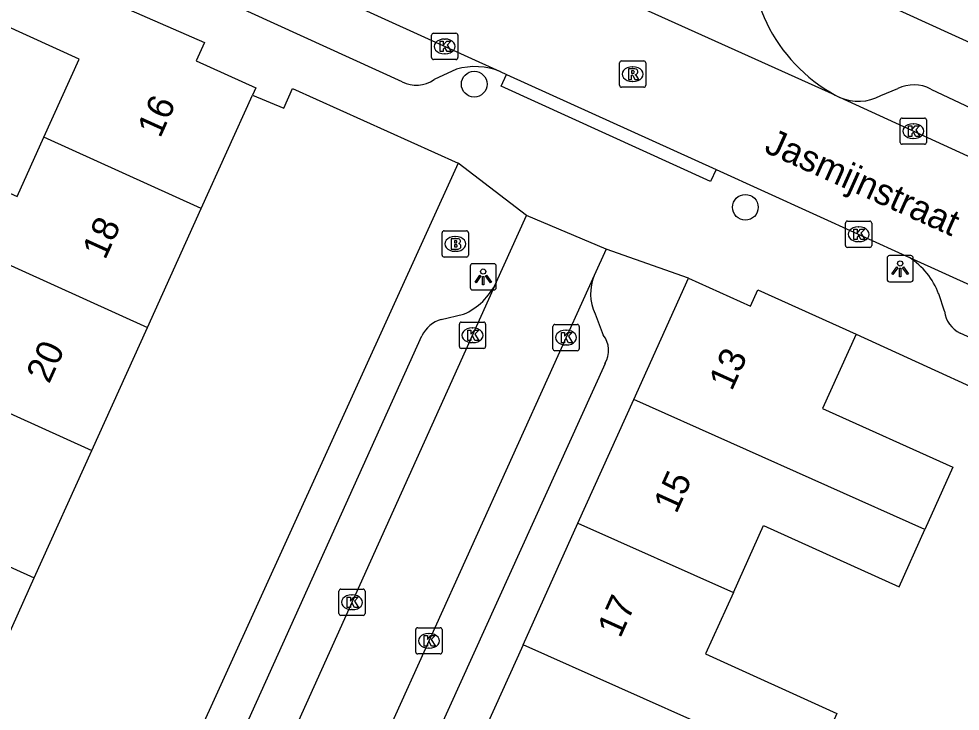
# Model space of a CAD drawing. Extents: x 161845 to 162341, y 381620 to 382158.
# Drawn here: x 162073.02 to 162108.87, y 381765.94 to 381792.29 of the extents above; entities that cross this region are included whole.
import ezdxf

# ---------------------------------------------------------------- set-up
doc = ezdxf.new("R2010")
doc.units = 0
for name, color, linetype in [('IMGEO_Boom', 7, 'Continuous'), ('IMGEO_Brandkraan', 7, 'Continuous'), ('IMGEO_Kolk', 7, 'Continuous'), ('IMGEO_Lichtpunt', 7, 'Continuous'), ('IMGEO_Muur', 7, 'Continuous'), ('IMGEO_Openbare_ruimte_label', 7, 'Continuous'), ('IMGEO_Pand', 7, 'Continuous'), ('IMGEO_Pand_nummerreeks', 7, 'Continuous'), ('IMGEO_Rijbaan_lokaal_open', 7, 'Continuous'), ('IMGEO_Rioolput', 7, 'Continuous'), ('IMGEO_Voetpad_open', 7, 'Continuous')]:
    doc.layers.add(name, color=color, linetype=linetype)

msp = doc.modelspace()

# ---------------------------------------------------------------- linework, layer by layer
at = {"layer": 'IMGEO_Boom'}
for centre in [(162090.359, 381789.808), (162100.687, 381785.121)]:
    msp.add_circle(centre, 0.489, dxfattribs=at)
at = {"layer": 'IMGEO_Brandkraan'}
for p, q in [((162089.138, 381783.301), (162089.138, 381784.153)), ((162089.213, 381784.227), (162090.065, 381784.227)), ((162089.626, 381784.007), (162089.651, 381784.007)), ((162090.139, 381784.153), (162090.139, 381783.301)), ((162089.649, 381783.447), (162089.624, 381783.447)), ((162090.065, 381783.227), (162089.213, 381783.227))]:
    msp.add_line(p, q, dxfattribs=at)
for points in [[(162089.138, 381783.301), (162089.138, 381784.153)], [(162089.213, 381784.227), (162090.065, 381784.227)], [(162090.139, 381784.153), (162090.139, 381783.301)], [(162089.486, 381783.927), (162089.486, 381783.527), (162089.699, 381783.527)], [(162089.717, 381783.927), (162089.486, 381783.927)], [(162089.665, 381783.846), (162089.611, 381783.846), (162089.611, 381783.77)], [(162089.611, 381783.77), (162089.664, 381783.77)], [(162089.673, 381783.694), (162089.611, 381783.694), (162089.611, 381783.613)], [(162089.611, 381783.613), (162089.673, 381783.613)], [(162090.065, 381783.227), (162089.213, 381783.227)]]:
    msp.add_lwpolyline(points, dxfattribs=at)
for centre, radius, start, end in [((162089.215, 381784.151), 0.0765, 91.552, 178.448), ((162089.215, 381784.151), 0.0765, 91.552, 178.448), ((162090.063, 381784.151), 0.0765, 1.552, 88.448), ((162090.063, 381784.151), 0.0765, 1.552, 88.448), ((162089.666, 381783.808), 0.0379, 267.8285, 90.9355), ((162089.674, 381783.653), 0.0404, 269.8759, 90.5077), ((162089.721, 381783.782), 0.145, 59.4692, 91.5367), ((162089.746, 381783.829), 0.0922, 285.5137, 58.1501), ((162089.751, 381783.637), 0.105, 301.3115, 78.989), ((162089.215, 381783.303), 0.0765, 181.552, 268.448), ((162089.215, 381783.303), 0.0765, 181.552, 268.448), ((162089.705, 381783.778), 0.251, 268.6676, 293.5347), ((162090.063, 381783.303), 0.0765, 271.552, 358.448), ((162090.063, 381783.303), 0.0765, 271.552, 358.448)]:
    msp.add_arc(centre, radius, start, end, dxfattribs=at)
for centre, major_axis, ratio, start_param, end_param in [((162089.625, 381783.727), (-0.387, 0.002), 0.722429, 4.712389, 7.853982), ((162089.65, 381783.727), (-0.39, 0.002), 0.717154, 1.570796, 4.712389)]:
    msp.add_ellipse(centre, major_axis=major_axis, ratio=ratio, start_param=start_param, end_param=end_param, dxfattribs=at)
at = {"layer": 'IMGEO_Kolk'}
for p, q in [((162088.737, 381790.82), (162088.737, 381791.672)), ((162088.812, 381791.746), (162089.664, 381791.746)), ((162089.225, 381791.526), (162089.25, 381791.526)), ((162089.738, 381791.672), (162089.738, 381790.82)), ((162089.248, 381790.966), (162089.223, 381790.966)), ((162089.664, 381790.746), (162088.812, 381790.746)), ((162106.584, 381787.594), (162106.584, 381788.446)), ((162106.659, 381788.52), (162107.511, 381788.52)), ((162107.072, 381788.3), (162107.097, 381788.3)), ((162107.585, 381788.446), (162107.585, 381787.594)), ((162107.095, 381787.74), (162107.07, 381787.74)), ((162107.511, 381787.52), (162106.659, 381787.52)), ((162104.497, 381783.668), (162104.497, 381784.52)), ((162104.572, 381784.594), (162105.424, 381784.594)), ((162104.985, 381784.374), (162105.01, 381784.374)), ((162105.498, 381784.52), (162105.498, 381783.668)), ((162105.424, 381783.594), (162104.572, 381783.594)), ((162105.008, 381783.814), (162104.983, 381783.814)), ((162089.868, 381780.75), (162090.72, 381780.75)), ((162089.793, 381779.824), (162089.793, 381780.676)), ((162090.281, 381780.53), (162090.306, 381780.53)), ((162090.794, 381780.676), (162090.794, 381779.824)), ((162093.357, 381779.736), (162093.357, 381780.588)), ((162093.432, 381780.662), (162094.284, 381780.662)), ((162093.845, 381780.442), (162093.87, 381780.442)), ((162094.358, 381780.588), (162094.358, 381779.736)), ((162090.72, 381779.75), (162089.868, 381779.75)), ((162090.304, 381779.97), (162090.279, 381779.97)), ((162094.284, 381779.662), (162093.432, 381779.662)), ((162093.868, 381779.882), (162093.843, 381779.882)), ((162085.204, 381769.662), (162085.204, 381770.514)), ((162085.279, 381770.588), (162086.131, 381770.588)), ((162085.692, 381770.368), (162085.717, 381770.368)), ((162086.205, 381770.514), (162086.205, 381769.662)), ((162085.715, 381769.808), (162085.69, 381769.808)), ((162086.131, 381769.588), (162085.279, 381769.588)), ((162088.134, 381768.195), (162088.134, 381769.047)), ((162088.209, 381769.121), (162089.061, 381769.121)), ((162088.622, 381768.901), (162088.647, 381768.901)), ((162089.135, 381769.047), (162089.135, 381768.195)), ((162088.645, 381768.341), (162088.62, 381768.341)), ((162089.061, 381768.121), (162088.209, 381768.121))]:
    msp.add_line(p, q, dxfattribs=at)
for points in [[(162088.737, 381790.82), (162088.737, 381791.672)], [(162088.812, 381791.746), (162089.664, 381791.746)], [(162089.738, 381791.672), (162089.738, 381790.82)], [(162089.058, 381791.446), (162089.181, 381791.446), (162089.181, 381791.295), (162089.311, 381791.446), (162089.475, 381791.446), (162089.329, 381791.295), (162089.482, 381791.046), (162089.33, 381791.046), (162089.245, 381791.21), (162089.181, 381791.143), (162089.181, 381791.046), (162089.058, 381791.046), (162089.058, 381791.446)], [(162089.664, 381790.746), (162088.812, 381790.746)], [(162106.584, 381787.594), (162106.584, 381788.446)], [(162106.659, 381788.52), (162107.511, 381788.52)], [(162107.585, 381788.446), (162107.585, 381787.594)], [(162106.905, 381788.22), (162107.028, 381788.22), (162107.028, 381788.069), (162107.158, 381788.22), (162107.322, 381788.22), (162107.176, 381788.069), (162107.329, 381787.82), (162107.177, 381787.82), (162107.092, 381787.984), (162107.028, 381787.917), (162107.028, 381787.82), (162106.905, 381787.82), (162106.905, 381788.22)], [(162107.511, 381787.52), (162106.659, 381787.52)], [(162104.497, 381783.668), (162104.497, 381784.52)], [(162104.572, 381784.594), (162105.424, 381784.594)], [(162105.498, 381784.52), (162105.498, 381783.668)], [(162104.818, 381784.294), (162104.941, 381784.294), (162104.941, 381784.143), (162105.071, 381784.294), (162105.235, 381784.294), (162105.089, 381784.143), (162105.242, 381783.894), (162105.09, 381783.894), (162105.005, 381784.058), (162104.941, 381783.991), (162104.941, 381783.894), (162104.818, 381783.894), (162104.818, 381784.294)], [(162105.424, 381783.594), (162104.572, 381783.594)], [(162089.868, 381780.75), (162090.72, 381780.75)], [(162089.793, 381779.824), (162089.793, 381780.676)], [(162090.114, 381780.45), (162090.237, 381780.45), (162090.237, 381780.299), (162090.367, 381780.45), (162090.531, 381780.45), (162090.385, 381780.299), (162090.538, 381780.05), (162090.386, 381780.05), (162090.301, 381780.214), (162090.237, 381780.147), (162090.237, 381780.05), (162090.114, 381780.05), (162090.114, 381780.45)], [(162090.794, 381780.676), (162090.794, 381779.824)], [(162093.357, 381779.736), (162093.357, 381780.588)], [(162093.432, 381780.662), (162094.284, 381780.662)], [(162094.358, 381780.588), (162094.358, 381779.736)], [(162093.678, 381780.362), (162093.801, 381780.362), (162093.801, 381780.211), (162093.931, 381780.362), (162094.095, 381780.362), (162093.949, 381780.211), (162094.102, 381779.962), (162093.95, 381779.962), (162093.865, 381780.126), (162093.801, 381780.059), (162093.801, 381779.962), (162093.678, 381779.962), (162093.678, 381780.362)], [(162090.72, 381779.75), (162089.868, 381779.75)], [(162094.284, 381779.662), (162093.432, 381779.662)], [(162085.204, 381769.662), (162085.204, 381770.514)], [(162085.279, 381770.588), (162086.131, 381770.588)], [(162086.205, 381770.514), (162086.205, 381769.662)], [(162085.525, 381770.288), (162085.648, 381770.288), (162085.648, 381770.137), (162085.778, 381770.288), (162085.942, 381770.288), (162085.796, 381770.137), (162085.949, 381769.888), (162085.797, 381769.888), (162085.712, 381770.052), (162085.648, 381769.985), (162085.648, 381769.888), (162085.525, 381769.888), (162085.525, 381770.288)], [(162086.131, 381769.588), (162085.279, 381769.588)], [(162088.134, 381768.195), (162088.134, 381769.047)], [(162088.209, 381769.121), (162089.061, 381769.121)], [(162089.135, 381769.047), (162089.135, 381768.195)], [(162088.455, 381768.821), (162088.578, 381768.821), (162088.578, 381768.67), (162088.708, 381768.821), (162088.872, 381768.821), (162088.726, 381768.67), (162088.879, 381768.421), (162088.727, 381768.421), (162088.642, 381768.585), (162088.578, 381768.518), (162088.578, 381768.421), (162088.455, 381768.421), (162088.455, 381768.821)], [(162089.061, 381768.121), (162088.209, 381768.121)]]:
    msp.add_lwpolyline(points, dxfattribs=at)
for centre, start, end in [((162088.814, 381791.67), 91.552, 178.448), ((162088.814, 381791.67), 91.552, 178.448), ((162089.662, 381791.67), 1.552, 88.448), ((162089.662, 381791.67), 1.552, 88.448), ((162088.814, 381790.822), 181.552, 268.448), ((162088.814, 381790.822), 181.552, 268.448), ((162089.662, 381790.822), 271.552, 358.448), ((162089.662, 381790.822), 271.552, 358.448), ((162106.661, 381788.444), 91.552, 178.448), ((162106.661, 381788.444), 91.552, 178.448), ((162107.509, 381788.444), 1.552, 88.448), ((162107.509, 381788.444), 1.552, 88.448), ((162106.661, 381787.596), 181.552, 268.448), ((162106.661, 381787.596), 181.552, 268.448), ((162107.509, 381787.596), 271.552, 358.448), ((162107.509, 381787.596), 271.552, 358.448), ((162104.574, 381784.518), 91.552, 178.448), ((162104.574, 381784.518), 91.552, 178.448), ((162105.422, 381784.518), 1.552, 88.448), ((162105.422, 381784.518), 1.552, 88.448), ((162104.574, 381783.67), 181.552, 268.448), ((162104.574, 381783.67), 181.552, 268.448), ((162105.422, 381783.67), 271.552, 358.448), ((162105.422, 381783.67), 271.552, 358.448), ((162089.87, 381780.674), 91.552, 178.448), ((162089.87, 381780.674), 91.552, 178.448), ((162090.718, 381780.674), 1.552, 88.448), ((162090.718, 381780.674), 1.552, 88.448), ((162093.434, 381780.586), 91.552, 178.448), ((162093.434, 381780.586), 91.552, 178.448), ((162094.282, 381780.586), 1.552, 88.448), ((162094.282, 381780.586), 1.552, 88.448), ((162089.87, 381779.826), 181.552, 268.448), ((162089.87, 381779.826), 181.552, 268.448), ((162090.718, 381779.826), 271.552, 358.448), ((162090.718, 381779.826), 271.552, 358.448), ((162093.434, 381779.738), 181.552, 268.448), ((162093.434, 381779.738), 181.552, 268.448), ((162094.282, 381779.738), 271.552, 358.448), ((162094.282, 381779.738), 271.552, 358.448), ((162085.281, 381770.512), 91.552, 178.448), ((162085.281, 381770.512), 91.552, 178.448), ((162086.129, 381770.512), 1.552, 88.448), ((162086.129, 381770.512), 1.552, 88.448), ((162085.281, 381769.664), 181.552, 268.448), ((162085.281, 381769.664), 181.552, 268.448), ((162086.129, 381769.664), 271.552, 358.448), ((162086.129, 381769.664), 271.552, 358.448), ((162088.211, 381769.045), 91.552, 178.448), ((162088.211, 381769.045), 91.552, 178.448), ((162089.059, 381769.045), 1.552, 88.448), ((162089.059, 381769.045), 1.552, 88.448), ((162088.211, 381768.197), 181.552, 268.448), ((162088.211, 381768.197), 181.552, 268.448), ((162089.059, 381768.197), 271.552, 358.448), ((162089.059, 381768.197), 271.552, 358.448)]:
    msp.add_arc(centre, 0.0765, start, end, dxfattribs=at)
for centre, major_axis, ratio, start_param, end_param in [((162089.224, 381791.246), (-0.387, 0.002), 0.722429, 4.712389, 7.853982), ((162089.249, 381791.246), (-0.39, 0.002), 0.717154, 1.570796, 4.712389), ((162107.071, 381788.02), (-0.387, 0.002), 0.722429, 4.712389, 7.853982), ((162107.096, 381788.02), (-0.39, 0.002), 0.717154, 1.570796, 4.712389), ((162104.984, 381784.094), (-0.387, 0.002), 0.722429, 4.712389, 7.853982), ((162105.009, 381784.094), (-0.39, 0.002), 0.717154, 1.570796, 4.712389), ((162090.28, 381780.25), (-0.387, 0.002), 0.722429, 4.712389, 7.853982), ((162090.305, 381780.25), (-0.39, 0.002), 0.717154, 1.570796, 4.712389), ((162093.844, 381780.162), (-0.387, 0.002), 0.722429, 4.712389, 7.853982), ((162093.869, 381780.162), (-0.39, 0.002), 0.717154, 1.570796, 4.712389), ((162085.691, 381770.088), (-0.387, 0.002), 0.722429, 4.712389, 7.853982), ((162085.716, 381770.088), (-0.39, 0.002), 0.717154, 1.570796, 4.712389), ((162088.621, 381768.621), (-0.387, 0.002), 0.722429, 4.712389, 7.853982), ((162088.646, 381768.621), (-0.39, 0.002), 0.717154, 1.570796, 4.712389)]:
    msp.add_ellipse(centre, major_axis=major_axis, ratio=ratio, start_param=start_param, end_param=end_param, dxfattribs=at)
at = {"layer": 'IMGEO_Lichtpunt'}
for p, q in [((162106.986, 381783.282), (162106.178, 381783.282)), ((162106.986, 381783.282), (162106.178, 381783.282)), ((162090.205, 381782.877), (162090.205, 381782.07)), ((162090.205, 381782.877), (162090.205, 381782.07)), ((162091.107, 381782.972), (162090.299, 381782.972)), ((162091.107, 381782.972), (162090.299, 381782.972)), ((162091.201, 381782.07), (162091.201, 381782.877)), ((162091.201, 381782.07), (162091.201, 381782.877)), ((162106.084, 381783.187), (162106.084, 381782.38)), ((162106.084, 381783.187), (162106.084, 381782.38)), ((162107.08, 381782.38), (162107.08, 381783.187)), ((162107.08, 381782.38), (162107.08, 381783.187)), ((162106.178, 381782.286), (162106.986, 381782.286)), ((162106.178, 381782.286), (162106.986, 381782.286)), ((162090.299, 381781.976), (162091.107, 381781.976)), ((162090.299, 381781.976), (162091.107, 381781.976))]:
    msp.add_line(p, q, dxfattribs=at)
for points in [[(162090.579, 381782.541), (162090.618, 381782.513), (162090.43, 381782.251), (162090.392, 381782.278), (162090.579, 381782.541)], [(162090.791, 381782.513), (162090.829, 381782.54), (162091.016, 381782.278), (162090.977, 381782.25), (162090.791, 381782.513)], [(162106.458, 381782.851), (162106.497, 381782.823), (162106.309, 381782.561), (162106.271, 381782.588), (162106.458, 381782.851)], [(162106.56, 381782.803), (162106.607, 381782.803), (162106.607, 381782.481), (162106.56, 381782.481), (162106.56, 381782.803)], [(162106.67, 381782.823), (162106.708, 381782.85), (162106.895, 381782.588), (162106.856, 381782.56), (162106.67, 381782.823)], [(162090.681, 381782.493), (162090.728, 381782.493), (162090.728, 381782.171), (162090.681, 381782.171), (162090.681, 381782.493)]]:
    msp.add_lwpolyline(points, dxfattribs=at)
for centre in [(162106.583, 381782.985), (162090.704, 381782.675)]:
    msp.add_circle(centre, 0.0994, dxfattribs=at)
for centre, start, end in [((162106.178, 381783.187), 90, 180), ((162106.178, 381783.187), 90, 180), ((162106.986, 381783.187), 0, 90), ((162106.986, 381783.187), 0, 90), ((162090.299, 381782.877), 90, 180), ((162090.299, 381782.877), 90, 180), ((162091.107, 381782.877), 0, 90), ((162091.107, 381782.877), 0, 90), ((162106.178, 381782.38), 180, 270), ((162106.178, 381782.38), 180, 270), ((162106.986, 381782.38), 270, 0), ((162106.986, 381782.38), 270, 360), ((162090.299, 381782.07), 180, 270), ((162090.299, 381782.07), 180, 270), ((162091.107, 381782.07), 270, 0), ((162091.107, 381782.07), 270, 360)]:
    msp.add_arc(centre, 0.0946, start, end, dxfattribs=at)
at = {"layer": 'IMGEO_Muur'}
msp.add_lwpolyline([(162104.902, 381780.293), (162119.551, 381773.591)], dxfattribs=at)
at = {"layer": 'IMGEO_Pand'}
for points in [[(162073.969, 381787.795), (162075.316, 381790.766), (162070.431, 381792.976), (162071.424, 381795.171)], [(162071.424, 381795.171), (162080.088, 381791.39), (162079.775, 381790.698), (162082.043, 381789.672), (162081.916, 381789.39)], [(162109.58, 381791.299), (162109.557, 381791.247), (162105.823, 381792.94), (162106.121, 381793.596), (162103.999, 381794.559)], [(162079.965, 381785.079), (162081.916, 381789.39)], [(162066.965, 381785.512), (162067.993, 381787.785), (162072.946, 381785.539), (162073.969, 381787.795)], [(162079.965, 381785.079), (162073.969, 381787.795)], [(162066.965, 381785.512), (162077.918, 381780.552)], [(162077.918, 381780.552), (162079.965, 381785.079)], [(162096.439, 381777.811), (162098.526, 381782.429)], [(162098.526, 381782.429), (162100.887, 381781.363), (162101.163, 381781.976), (162104.902, 381780.293)], [(162075.797, 381775.863), (162077.918, 381780.552)], [(162104.902, 381780.293), (162103.63, 381777.467), (162108.591, 381775.234), (162107.525, 381772.865)], [(162069.789, 381778.584), (162075.797, 381775.863)], [(162094.311, 381773.1), (162096.439, 381777.811)], [(162107.525, 381772.865), (162096.439, 381777.811)], [(162062.654, 381775.972), (162073.603, 381771.013)], [(162073.603, 381771.013), (162075.797, 381775.863)], [(162092.219, 381768.471), (162094.311, 381773.1)], [(162094.311, 381773.1), (162100.229, 381770.46)], [(162100.229, 381770.46), (162101.379, 381773.006), (162106.539, 381770.675), (162107.525, 381772.865)], [(162071.478, 381766.316), (162073.603, 381771.013)], [(162100.229, 381770.46), (162099.172, 381768.121), (162104.172, 381765.858), (162103.149, 381763.595)], [(162092.219, 381768.471), (162090.043, 381763.653)], [(162103.149, 381763.595), (162092.219, 381768.471)]]:
    msp.add_lwpolyline(points, dxfattribs=at)
at = {"layer": 'IMGEO_Rijbaan_lokaal_open'}
for points in [[(162072.256, 381798.955), (162091.347, 381790.291)], [(162104.113, 381789.392), (162091.158, 381795.22), (162090.301, 381795.665)], [(162091.347, 381790.291), (162091.591, 381790.18)], [(162091.591, 381790.18), (162099.57, 381786.559)], [(162104.113, 381789.392), (162104.279, 381789.306)], [(162122.866, 381780.786), (162104.279, 381789.306)], [(162099.57, 381786.559), (162106.934, 381783.216)], [(162091.2, 381782.254), (162092.357, 381784.815)], [(162095.383, 381783.532), (162092.357, 381784.815)], [(162095.383, 381783.532), (162094.929, 381782.528)], [(162106.934, 381783.216), (162121.187, 381776.749)], [(162094.929, 381782.528), (162080.868, 381751.463)], [(162091.2, 381782.254), (162077.885, 381752.773)]]:
    msp.add_lwpolyline(points, dxfattribs=at)
msp.add_arc((162107.129, 381794.886), 6.268, 170.9532, 241.2394, dxfattribs=at)
at = {"layer": 'IMGEO_Rioolput'}
for p, q in [((162095.893, 381789.765), (162095.893, 381790.617)), ((162095.968, 381790.691), (162096.82, 381790.691)), ((162096.381, 381790.471), (162096.406, 381790.471)), ((162096.894, 381790.617), (162096.894, 381789.765)), ((162096.82, 381789.691), (162095.968, 381789.691)), ((162096.404, 381789.911), (162096.379, 381789.911))]:
    msp.add_line(p, q, dxfattribs=at)
for points in [[(162095.893, 381789.765), (162095.893, 381790.617)], [(162095.968, 381790.691), (162096.82, 381790.691)], [(162096.894, 381790.617), (162096.894, 381789.765)], [(162096.482, 381790.389), (162096.23, 381790.391), (162096.23, 381789.991)], [(162096.23, 381789.991), (162096.354, 381789.991), (162096.354, 381790.153), (162096.365, 381790.153)], [(162096.408, 381790.31), (162096.354, 381790.31), (162096.354, 381790.229)], [(162096.354, 381790.229), (162096.406, 381790.229)], [(162096.412, 381790.124), (162096.483, 381789.991), (162096.623, 381789.991), (162096.558, 381790.117)], [(162096.82, 381789.691), (162095.968, 381789.691)]]:
    msp.add_lwpolyline(points, dxfattribs=at)
for centre, radius, start, end in [((162095.97, 381790.615), 0.0765, 91.552, 178.448), ((162095.97, 381790.615), 0.0765, 91.552, 178.448), ((162096.818, 381790.615), 0.0765, 1.552, 88.448), ((162096.818, 381790.615), 0.0765, 1.552, 88.448), ((162096.364, 381790.1), 0.0533, 26.0293, 88.6989), ((162096.39, 381790.418), 0.19, 274.7715, 282.9687), ((162096.414, 381790.214), 0.0964, 77.0061, 93.1865), ((162096.428, 381790.271), 0.0378, 276.6634, 79.6772), ((162096.481, 381790.279), 0.109, 350.3612, 89.416), ((162096.479, 381790.279), 0.112, 277.5842, 350.9817), ((162096.463, 381790.064), 0.108, 29.5134, 73.7905), ((162095.97, 381789.767), 0.0765, 181.552, 268.448), ((162095.97, 381789.767), 0.0765, 181.552, 268.448), ((162096.818, 381789.767), 0.0765, 271.552, 358.448), ((162096.818, 381789.767), 0.0765, 271.552, 358.448)]:
    msp.add_arc(centre, radius, start, end, dxfattribs=at)
for centre, major_axis, ratio, start_param, end_param in [((162096.38, 381790.191), (-0.387, 0.002), 0.722429, 4.712389, 7.853982), ((162096.405, 381790.191), (-0.39, 0.002), 0.717154, 1.570796, 4.712389)]:
    msp.add_ellipse(centre, major_axis=major_axis, ratio=ratio, start_param=start_param, end_param=end_param, dxfattribs=at)
at = {"layer": 'IMGEO_Voetpad_open'}
for points in [[(162087.616, 381789.9), (162074.274, 381795.987)], [(162089.683, 381790.379), (162088.834, 381789.981)], [(162099.57, 381786.559), (162099.362, 381786.105), (162091.383, 381789.727), (162091.591, 381790.18)], [(162081.916, 381789.39), (162083.105, 381788.89), (162083.445, 381789.649), (162089.747, 381786.804)], [(162105.846, 381789.382), (162106.493, 381789.639)], [(162107.749, 381789.619), (162121.232, 381783.278)], [(162089.747, 381786.804), (162074.49, 381753.282)], [(162092.357, 381784.815), (162089.747, 381786.804)], [(162098.526, 381782.429), (162095.383, 381783.532)], [(162108.268, 381781.166), (162108.049, 381781.825)], [(162089.101, 381780.855), (162089.951, 381781.049)], [(162094.965, 381781.071), (162095.273, 381780.26)], [(162077.427, 381756), (162088.368, 381780.23)], [(162104.902, 381780.293), (162119.551, 381773.591)], [(162117.733, 381776.281), (162108.868, 381780.331)], [(162095.341, 381779.181), (162086.211, 381759.034), (162085.08, 381759.486), (162084.665, 381758.456), (162085.708, 381757.978), (162083.457, 381752.979)]]:
    msp.add_lwpolyline(points, dxfattribs=at)
for centre, radius, start, end in [((162090.385, 381787.877), 2.599, 68.2733, 105.6722), ((162088.156, 381790.978), 1.206, 243.3981, 304.2114), ((162107.102, 381788.408), 1.374, 61.8767, 116.2988), ((162104.988, 381790.873), 1.72, 245.6503, 299.9031), ((162105.379, 381780.827), 2.85, 20.4894, 56.9406), ((162096.582, 381781.84), 1.79, 157.3937, 205.4371), ((162088.925, 381783.362), 2.53, 293.914, 334.0316), ((162109.327, 381781.294), 1.066, 186.8751, 244.5241), ((162089.438, 381779.717), 1.187, 106.5113, 154.3945), ((162094.541, 381779.672), 0.938, 328.4363, 38.7758)]:
    msp.add_arc(centre, radius, start, end, dxfattribs=at)

# ---------------------------------------------------------------- texts
at = {"layer": 'IMGEO_Openbare_ruimte_label'}
msp.add_text('Jasmijnstraat', height=1, rotation=335.7932, dxfattribs=at).set_placement((162101.36, 381787.241))
at = {"layer": 'IMGEO_Pand_nummerreeks'}
for s, rotation, p in [('16', 65.661, (162078.397, 381787.724)), ('18', 65.661, (162076.302, 381783.093)), ('20', 65.661, (162074.168, 381778.376)), ('13', 65.6857, (162100.169, 381778.1)), ('15', 65.6857, (162098.057, 381773.425)), ('17', 65.6839, (162095.919, 381768.692))]:
    msp.add_text(s, height=1, rotation=rotation, dxfattribs=at).set_placement(p)

doc.saveas('drawing.dxf')
